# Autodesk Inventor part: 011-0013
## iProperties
Created: 2007-02
Part Number: 011-0013
Document SubType Name: Modeling
Designer: GG5883
Material: 34 Cr Mo 4
Description: Mors fixe
Stock Number: 11-0013
Checked By: GG5883
Author: GG5883
Revision Number: 00
Title: MORS FIXE
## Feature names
1. Volume base [Extrusion]
2. Découpe frontale [Extrusion]
3. découpe en vé [Extrusion]
4. Perçages fixation mors [Hole]
